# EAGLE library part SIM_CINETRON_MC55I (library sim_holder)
DRZAK SIM KARTY PRO MC55I
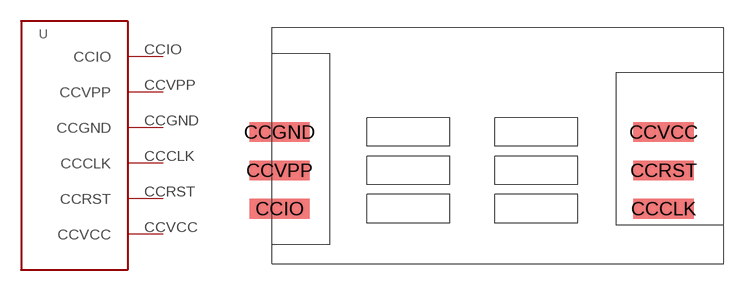
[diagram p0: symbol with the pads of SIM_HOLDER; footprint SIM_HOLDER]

Designator prefix -

## SIM_CINETRON_MC55I  [SIM_HOLDER]
CCCLK  CCCLK
CCGND  CCGND  pwr
CCIO  CCIO
CCRST  CCRST
CCVCC  CCVCC
CCVPP  CCVPP  pwr

## Footprint SIM_HOLDER (pad centres in mm)
smd 4 x 1.3: CCCLK 26,3.65; CCGND 0.5,8.73; CCIO 0.5,3.65; CCRST 26,6.19; CCVCC 26,8.73; CCVPP 0.5,6.19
